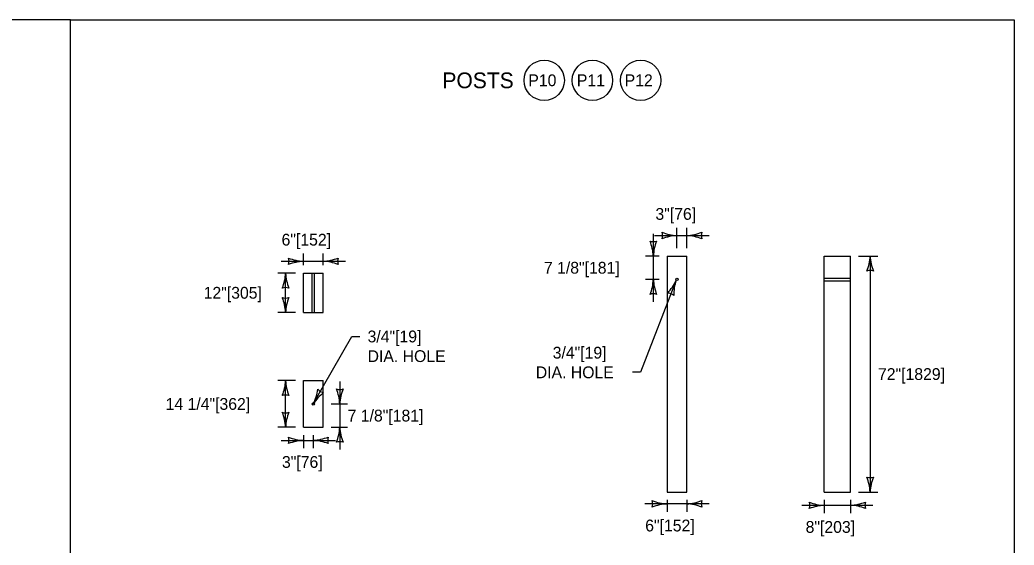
# Model space of a CAD drawing. Extents: x 49991 to 50160, y 49948 to 50051.
# Drawn here: x 50005.88 to 50010.94, y 49990.69 to 49993.36 of the extents above; entities that cross this region are included whole.
import ezdxf

# ---------------------------------------------------------------- set-up
doc = ezdxf.new("R2010")
doc.units = 0
for name, color, linetype in [('Level 1', 7, 'Continuous'), ('Level 2', 7, 'Continuous'), ('Level 3', 7, 'Continuous'), ('Level 4', 7, 'Continuous')]:
    doc.layers.add(name, color=color, linetype=linetype)

msp = doc.modelspace()

# ---------------------------------------------------------------- linework, layer by layer
at = {"layer": 'Level 1'}
for p, q in [((50009.172, 49992.1569), (50009.172, 49990.9569)), ((50009.172, 49992.1569), (50009.272, 49992.1569)), ((50009.272, 49990.9569), (50009.272, 49992.1569)), ((50009.971, 49990.9569), (50009.971, 49992.1569)), ((50009.971, 49992.1569), (50010.1044, 49992.1569)), ((50010.1044, 49990.9569), (50010.1044, 49992.1569)), ((50007.3228, 49991.8703), (50007.3228, 49992.0703)), ((50007.3228, 49992.0703), (50007.4228, 49992.0703)), ((50007.4228, 49991.8703), (50007.4228, 49992.0703)), ((50007.3228, 49991.8703), (50007.4228, 49991.8703)), ((50007.3228, 49991.2864), (50007.3228, 49991.5239)), ((50007.3228, 49991.5239), (50007.4228, 49991.5239)), ((50007.4228, 49991.2864), (50007.4228, 49991.5239)), ((50007.3228, 49991.2864), (50007.4228, 49991.2864)), ((50009.172, 49990.9569), (50009.272, 49990.9569)), ((50009.971, 49990.9569), (50010.1044, 49990.9569))]:
    msp.add_line(p, q, dxfattribs=at)
for points in [[(50006.1377, 49990.2991), (50006.1377, 49993.358), (49999.3835, 49993.358)], [(50006.1377, 49993.358), (50010.9365, 49993.358), (50010.9365, 49987.7988)]]:
    msp.add_lwpolyline(points, dxfattribs=at)
for centre in [(50009.222, 49992.0382), (50007.3728, 49991.4051)]:
    msp.add_circle(centre, 0.00625, dxfattribs=at)
at = {"layer": 'Level 2'}
for centre in [(50008.5469, 49993.0506), (50008.7921, 49993.0506), (50009.0374, 49993.0506)]:
    msp.add_circle(centre, 0.1026, dxfattribs=at)
at = {"layer": 'Level 3'}
for p, q in [((50009.222, 49992.1969), (50009.222, 49992.3013)), ((50009.272, 49992.1969), (50009.272, 49992.3013)), ((50009.1018, 49992.2704), (50009.1018, 49991.9248)), ((50009.1086, 49992.2613), (50009.3855, 49992.2613)), ((50007.2094, 49992.1303), (50007.5362, 49992.1303)), ((50007.3228, 49992.1103), (50007.3228, 49992.1703)), ((50007.4228, 49992.1103), (50007.4228, 49992.1703)), ((50009.132, 49992.1569), (50009.0618, 49992.1569)), ((50010.1444, 49992.1569), (50010.2443, 49992.1569)), ((50010.2043, 49992.1569), (50010.2043, 49990.9569)), ((50007.2828, 49992.0703), (50007.1919, 49992.0703)), ((50007.2319, 49991.8703), (50007.2319, 49992.0703)), ((50009.2176, 49992.0338), (50009.0366, 49991.5658)), ((50009.132, 49992.0382), (50009.0618, 49992.0382)), ((50007.2828, 49991.8703), (50007.1919, 49991.8703)), ((50007.3728, 49991.4051), (50007.5687, 49991.7482)), ((50007.5687, 49991.7482), (50007.6087, 49991.7482)), ((50007.2828, 49991.5239), (50007.1919, 49991.5239)), ((50007.2319, 49991.2864), (50007.2319, 49991.5239)), ((50009.0366, 49991.5658), (50008.9966, 49991.5658)), ((50007.5073, 49991.5186), (50007.5073, 49991.1729)), ((50007.4628, 49991.4051), (50007.5473, 49991.4051)), ((50007.2828, 49991.2864), (50007.1919, 49991.2864)), ((50007.4628, 49991.2864), (50007.5473, 49991.2864)), ((50007.2094, 49991.22), (50007.4862, 49991.22)), ((50007.3228, 49991.2464), (50007.3228, 49991.18)), ((50007.3728, 49991.2464), (50007.3728, 49991.18)), ((50009.172, 49990.9169), (50009.172, 49990.8569)), ((50009.272, 49990.9169), (50009.272, 49990.8569)), ((50009.971, 49990.9169), (50009.971, 49990.8495)), ((50010.1044, 49990.9169), (50010.1044, 49990.8495)), ((50010.1444, 49990.9569), (50010.2443, 49990.9569)), ((50009.3855, 49990.8969), (50009.0586, 49990.8969)), ((50009.8576, 49990.8895), (50010.2178, 49990.8895))]:
    msp.add_line(p, q, dxfattribs=at)
for centre, radius, start, end in [((50009.1018, 49992.2852), 0.0548, 252.1388, 287.8612), ((50008.8691, 49992.1455), 0.233, 2.8273, 22.0772), ((50009.324, 49992.1478), 0.2223, 157.456, 177.6395), ((50009.2312, 49992.4835), 0.2223, 247.456, 267.6395), ((50009.0938, 49992.2613), 0.0548, 342.1388, 17.8612), ((50009.2335, 49992.0286), 0.233, 92.8273, 112.0772), ((50009.2606, 49992.494), 0.233, 272.8273, 292.0772), ((50009.2629, 49992.0392), 0.2223, 67.456, 87.6395), ((50009.4003, 49992.2613), 0.0548, 162.1388, 197.8612), ((50007.3319, 49992.3525), 0.2223, 247.456, 267.6395), ((50007.1946, 49992.1303), 0.0548, 342.1388, 17.8612), ((50007.3343, 49991.8976), 0.233, 92.8273, 112.0772), ((50007.4113, 49992.363), 0.233, 272.8273, 292.0772), ((50007.4136, 49991.9082), 0.2223, 67.456, 87.6395), ((50007.551, 49992.1303), 0.0548, 162.1388, 197.8612), ((50009.9822, 49992.1661), 0.2223, 337.456, 357.6395), ((50010.437, 49992.1684), 0.233, 182.8273, 202.0772), ((50010.2043, 49992.0287), 0.0548, 72.1388, 107.8612), ((50007.0098, 49992.0795), 0.2223, 337.456, 357.6395), ((50007.4646, 49992.0818), 0.233, 182.8273, 202.0772), ((50008.8797, 49992.0474), 0.2223, 337.456, 357.6395), ((50009.3346, 49992.0497), 0.233, 182.8273, 202.0772), ((50009.0138, 49992.1224), 0.2223, 316.3102, 336.4937), ((50009.4388, 49991.9605), 0.233, 161.6815, 180.9313), ((50007.2319, 49991.9421), 0.0548, 72.1388, 107.8612), ((50007.2319, 49991.9985), 0.0548, 252.1388, 287.8612), ((50006.9992, 49991.8588), 0.233, 2.8273, 22.0772), ((50007.454, 49991.8612), 0.2223, 157.456, 177.6395), ((50009.1018, 49991.91), 0.0548, 72.1388, 107.8612), ((50009.1714, 49991.9142), 0.0548, 50.993, 86.7153), ((50007.0098, 49991.533), 0.2223, 337.456, 357.6395), ((50007.4646, 49991.5354), 0.233, 182.8273, 202.0772), ((50007.165, 49991.5105), 0.233, 333.1067, 352.3566), ((50007.4364, 49991.5165), 0.0548, 222.4182, 258.1406), ((50007.5073, 49991.5333), 0.0548, 252.1388, 287.8612), ((50007.2746, 49991.3936), 0.233, 2.8273, 22.0772), ((50007.7295, 49991.396), 0.2223, 157.456, 177.6395), ((50007.2319, 49991.3957), 0.0548, 72.1388, 107.8612), ((50007.5612, 49991.287), 0.2223, 127.7354, 147.9189), ((50007.2319, 49991.4146), 0.0548, 252.1388, 287.8612), ((50006.9992, 49991.2749), 0.233, 2.8273, 22.0772), ((50007.454, 49991.2772), 0.2223, 157.456, 177.6395), ((50007.2852, 49991.2955), 0.2223, 337.456, 357.6395), ((50007.74, 49991.2979), 0.233, 182.8273, 202.0772), ((50007.3319, 49991.4421), 0.2223, 247.456, 267.6395), ((50007.1946, 49991.22), 0.0548, 342.1388, 17.8612), ((50007.3343, 49990.9873), 0.233, 92.8273, 112.0772), ((50007.3613, 49991.4527), 0.233, 272.8273, 292.0772), ((50007.3636, 49990.9978), 0.2223, 67.456, 87.6395), ((50007.501, 49991.22), 0.0548, 162.1388, 197.8612), ((50007.5073, 49991.1582), 0.0548, 72.1388, 107.8612), ((50010.2043, 49991.0852), 0.0548, 252.1388, 287.8612), ((50009.9716, 49990.9455), 0.233, 2.8273, 22.0772), ((50010.4265, 49990.9478), 0.2223, 157.456, 177.6395), ((50009.1812, 49991.1191), 0.2223, 247.456, 267.6395), ((50009.0438, 49990.8969), 0.0548, 342.1388, 17.8612), ((50009.1835, 49990.6642), 0.233, 92.8273, 112.0772), ((50009.2606, 49991.1297), 0.233, 272.8273, 292.0772), ((50009.2629, 49990.6748), 0.2223, 67.456, 87.6395), ((50009.4003, 49990.8969), 0.0548, 162.1388, 197.8612), ((50009.9802, 49991.1116), 0.2223, 247.456, 267.6395), ((50009.8428, 49990.8895), 0.0548, 342.1388, 17.8612), ((50009.9825, 49990.6568), 0.233, 92.8273, 112.0772), ((50010.0929, 49991.1222), 0.233, 272.8273, 292.0772), ((50010.0952, 49990.6674), 0.2223, 67.456, 87.6395), ((50010.2326, 49990.8895), 0.0548, 162.1388, 197.8612)]:
    msp.add_arc(centre, radius, start, end, dxfattribs=at)
at = {"layer": 'Level 4'}
for p, q in [((50007.3665, 49991.8703), (50007.3665, 49992.0703)), ((50007.379, 49991.8703), (50007.379, 49992.0703)), ((50009.971, 49992.0444), (50010.1044, 49992.0444)), ((50009.971, 49992.0319), (50010.1044, 49992.0319))]:
    msp.add_line(p, q, dxfattribs=at)

# ---------------------------------------------------------------- texts
at = {"layer": 'Level 2'}
for s, height, p in [('POSTS', 0.08, (50008.0292, 49993.0106)), ('P10', 0.06, (50008.4662, 49993.0208)), ('P11', 0.06, (50008.713, 49993.0209)), ('P12', 0.06, (50008.9562, 49993.0209)), ('3"[76]', 0.06, (50009.1125, 49992.3413)), ('6"[152]', 0.06, (50007.2113, 49992.2103)), ('7 1/8"[181]', 0.06, (50008.5455, 49992.0676)), ('12"[305]', 0.06, (50006.8151, 49991.9403)), ('3/4"[19]', 0.06, (50007.6487, 49991.7182)), ('DIA. HOLE', 0.06, (50007.6487, 49991.6182)), ('3/4"[19]', 0.06, (50008.5901, 49991.6358)), ('DIA. HOLE', 0.06, (50008.504, 49991.5358)), ('72"[1829]', 0.06, (50010.2443, 49991.5269)), ('14 1/4"[362]', 0.06, (50006.6217, 49991.3751)), ('7 1/8"[181]', 0.06, (50007.5473, 49991.3157)), ('3"[76]', 0.06, (50007.2133, 49991.08)), ('6"[152]', 0.06, (50009.0606, 49990.7569)), ('8"[203]', 0.06, (50009.8763, 49990.7495))]:
    msp.add_text(s, height=height, dxfattribs=at).set_placement(p)

doc.saveas('drawing.dxf')
